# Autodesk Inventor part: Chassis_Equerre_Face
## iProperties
Created: 2009-01
Part Number: Chassis_Equerre_Face
Document SubType Name: Sheet Metal
Designer: claivier
Author: claivier
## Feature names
1. Chanfrein de coin1
2. Perçage1 [Hole]
3. Perçage2 [Hole]
4. Perçage3 [Hole]
5. Plaque1
6. Pli1
7. Couper1
8. Couper2
